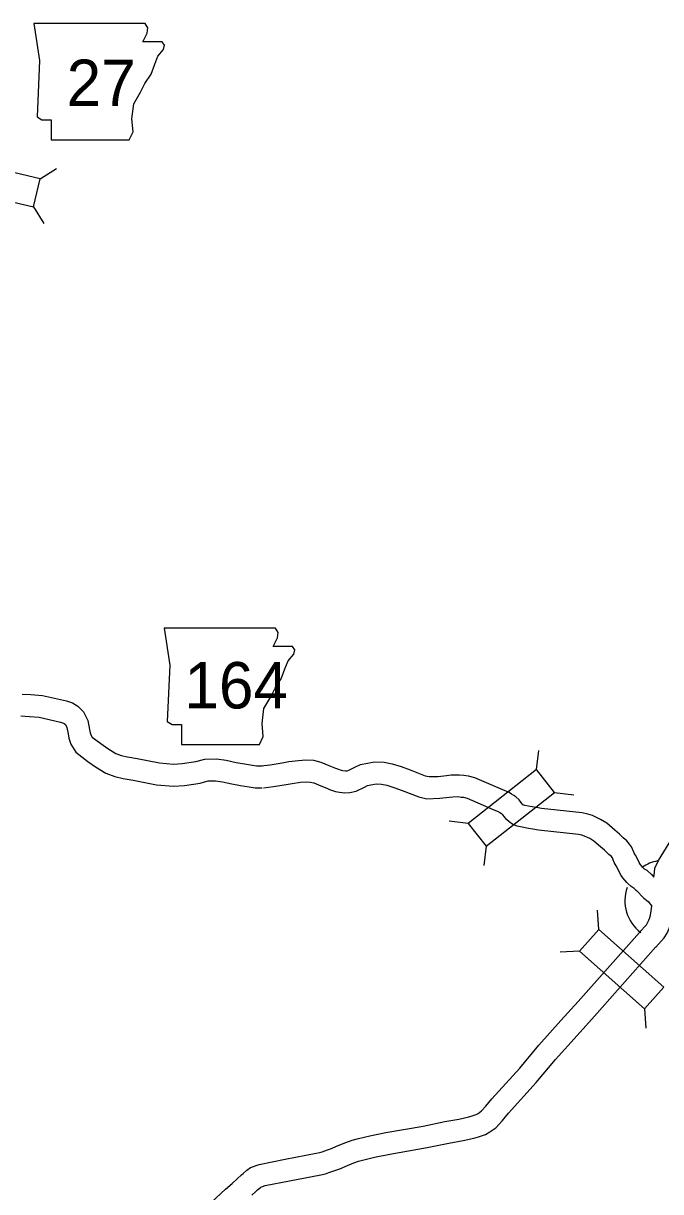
# Model space of a CAD drawing. Extents: x 1374139 to 1377472, y 1168351 to 1170484.
# Drawn here: x 1374646.9 to 1374734, y 1170176.4 to 1170336 of the extents above; entities that cross this region are included whole.
import ezdxf

# ---------------------------------------------------------------- set-up
doc = ezdxf.new("R2010")
doc.units = 0
doc.layers.add('Default', color=7, linetype='Continuous')

msp = doc.modelspace()

# ---------------------------------------------------------------- linework, layer by layer
at = {"layer": 'Default'}
for p, q in [((1374649.22, 1170314.78), (1374651.46, 1170316.17)), ((1374648.31, 1170310.92), (1374649.71, 1170308.68)), ((1374717.02, 1170234.05), (1374717.33, 1170236.67)), ((1374719.47, 1170230.94), (1374722.09, 1170230.62)), ((1374707.68, 1170226.7), (1374705.06, 1170227.01)), ((1374710.13, 1170223.59), (1374709.82, 1170220.96)), ((1374725.5, 1170212.22), (1374725.34, 1170214.86)), ((1374722.88, 1170209.26), (1374720.24, 1170209.1)), ((1374731.76, 1170201.38), (1374731.92, 1170198.74))]:
    msp.add_line(p, q, dxfattribs=at)
for points in [[(1374648.38, 1170336.01), (1374649.14, 1170330.93), (1374648.8, 1170323.23), (1374649.48, 1170322.81), (1374650.75, 1170322.81), (1374650.75, 1170320.1), (1374661.4, 1170320.1), (1374661.91, 1170321.2), (1374661.74, 1170322.98), (1374662, 1170325.01), (1374662.93, 1170326.62), (1374663.52, 1170327.8), (1374664.37, 1170329.07), (1374664.87, 1170330.42), (1374665.3, 1170331.52), (1374666.06, 1170332.45), (1374666.23, 1170333.05), (1374665.89, 1170333.47), (1374663.27, 1170333.47), (1374663.86, 1170334.65), (1374663.94, 1170335.41), (1374663.59, 1170336)], [(1374649.22, 1170314.78), (1374637.65, 1170317.48), (1374636.75, 1170313.62), (1374648.31, 1170310.92)], [(1374666.17, 1170253.39), (1374666.93, 1170248.32), (1374666.59, 1170240.62), (1374667.27, 1170240.2), (1374668.53, 1170240.2), (1374668.53, 1170237.49), (1374679.19, 1170237.49), (1374679.7, 1170238.59), (1374679.53, 1170240.37), (1374679.79, 1170242.4), (1374680.72, 1170244.01), (1374681.31, 1170245.19), (1374682.15, 1170246.46), (1374682.66, 1170247.81), (1374683.08, 1170248.91), (1374683.85, 1170249.84), (1374684.01, 1170250.43), (1374683.68, 1170250.86), (1374681.05, 1170250.86), (1374681.65, 1170252.04), (1374681.73, 1170252.8), (1374681.38, 1170253.39)], [(1374710.13, 1170223.59), (1374719.47, 1170230.94), (1374717.02, 1170234.05), (1374707.68, 1170226.7)], [(1374722.88, 1170209.26), (1374731.76, 1170201.38), (1374734.39, 1170204.34), (1374725.5, 1170212.22)]]:
    msp.add_lwpolyline(points, close=True, dxfattribs=at)
for points in [[(1374646.79, 1170244.37), (1374647.97, 1170244.32), (1374649.56, 1170244.18), (1374652.82, 1170243.44), (1374653.65, 1170243.16), (1374654.37, 1170242.74), (1374655.17, 1170241.95), (1374655.72, 1170240.77), (1374655.99, 1170239.53), (1374656.06, 1170239.1), (1374656.17, 1170238.79), (1374656.35, 1170238.5), (1374657.52, 1170237.6), (1374658.45, 1170236.95), (1374659.55, 1170236.26), (1374660.29, 1170235.99), (1374661.15, 1170235.79), (1374662.48, 1170235.59), (1374665.53, 1170234.96), (1374667.45, 1170234.8), (1374668.6, 1170234.88), (1374670.49, 1170235.16), (1374671.73, 1170235.5), (1374673.32, 1170235.52), (1374674.65, 1170235.35), (1374676, 1170235.03), (1374677.12, 1170234.84), (1374678.23, 1170234.64), (1374678.78, 1170234.57), (1374679.53, 1170234.57)], [(1374646.61, 1170241.38), (1374647.78, 1170241.33), (1374649.09, 1170241.21), (1374652.01, 1170240.55), (1374652.4, 1170240.42), (1374652.53, 1170240.34), (1374652.67, 1170240.2), (1374652.86, 1170239.81), (1374653.04, 1170238.95), (1374653.15, 1170238.34), (1374653.44, 1170237.51), (1374654.09, 1170236.45), (1374655.75, 1170235.18), (1374656.79, 1170234.45), (1374658.22, 1170233.56), (1374659.42, 1170233.11), (1374660.58, 1170232.84), (1374661.95, 1170232.63), (1374665.1, 1170231.99), (1374667.44, 1170231.79), (1374668.93, 1170231.9), (1374671.1, 1170232.22), (1374672.16, 1170232.5), (1374673.15, 1170232.52), (1374674.11, 1170232.39), (1374675.4, 1170232.09), (1374676.6, 1170231.88), (1374677.76, 1170231.68), (1374678.59, 1170231.57), (1374679.55, 1170231.57)], [(1374679.36, 1170234.56), (1374680.66, 1170234.72), (1374682.29, 1170234.98), (1374683.18, 1170235.14), (1374684.5, 1170235.31), (1374685.5, 1170235.38), (1374686.54, 1170235.35), (1374687.54, 1170235.08), (1374688.66, 1170234.63), (1374689.58, 1170234.27), (1374689.85, 1170234.14), (1374690.33, 1170233.98), (1374690.58, 1170233.93), (1374690.91, 1170233.89), (1374691.13, 1170233.9), (1374691.37, 1170233.96), (1374692.2, 1170234.37), (1374692.99, 1170234.74), (1374694.89, 1170235.11), (1374696.19, 1170235.06), (1374697.29, 1170234.86), (1374698.52, 1170234.46), (1374699.74, 1170234.01), (1374701.82, 1170233.21), (1374702.34, 1170233.09), (1374703.57, 1170233.12), (1374704.7, 1170233.25), (1374705.34, 1170233.35), (1374706.45, 1170233.36), (1374707.08, 1170233.29), (1374707.66, 1170233.22), (1374708.55, 1170232.96), (1374712.36, 1170231.32)], [(1374679.72, 1170231.58), (1374681.08, 1170231.75), (1374682.8, 1170232.02), (1374683.64, 1170232.17), (1374684.79, 1170232.32), (1374685.55, 1170232.37), (1374686.11, 1170232.36), (1374686.59, 1170232.23), (1374687.55, 1170231.84), (1374688.38, 1170231.52), (1374688.73, 1170231.35), (1374689.54, 1170231.08), (1374690.11, 1170230.96), (1374690.83, 1170230.88), (1374691.52, 1170230.92), (1374692.36, 1170231.1), (1374693.51, 1170231.67), (1374693.93, 1170231.87), (1374695.12, 1170232.1), (1374695.86, 1170232.07), (1374696.56, 1170231.94), (1374697.54, 1170231.62), (1374698.68, 1170231.21), (1374700.94, 1170230.33), (1374702.05, 1170230.08), (1374703.79, 1170230.13), (1374705.1, 1170230.28), (1374705.58, 1170230.35), (1374706.3, 1170230.36), (1374706.73, 1170230.31), (1374707.04, 1170230.27), (1374707.53, 1170230.13), (1374711.18, 1170228.57)], [(1374732.69, 1170219.73), (1374732.1, 1170220.25), (1374731.76, 1170220.45), (1374731.56, 1170220.65), (1374731.5, 1170220.71), (1374731.34, 1170220.89), (1374731.19, 1170221.07), (1374731.15, 1170221.14), (1374731.03, 1170221.36), (1374730.82, 1170221.78), (1374730.5, 1170222.37), (1374730.33, 1170222.66), (1374730.29, 1170222.79), (1374729.99, 1170223.51), (1374729.72, 1170223.87), (1374729.36, 1170224.33), (1374728.86, 1170224.72), (1374728.33, 1170225.24), (1374727.7, 1170225.78), (1374726.59, 1170226.75), (1374725.75, 1170227.23), (1374725.31, 1170227.48), (1374724.64, 1170227.78), (1374724.01, 1170227.98), (1374723.25, 1170228.17), (1374717.69, 1170228.75), (1374717.01, 1170228.87), (1374716.42, 1170228.98), (1374715.43, 1170229.15), (1374715.26, 1170229.2), (1374715.16, 1170229.24), (1374715.15, 1170229.24), (1374715, 1170229.43), (1374714.62, 1170229.91), (1374714.17, 1170230.34), (1374713.91, 1170230.52), (1374713.6, 1170230.72), (1374713.27, 1170230.91), (1374712.39, 1170231.31)], [(1374733.04, 1170219.38), (1374733.09, 1170219.67), (1374733.1, 1170220), (1374733.17, 1170220.57), (1374733.67, 1170221.64), (1374735.14, 1170224.02), (1374735.33, 1170224.39), (1374735.84, 1170224.99), (1374736.32, 1170225.29), (1374746.81, 1170231.97)], [(1374730.68, 1170217.51), (1374730.32, 1170217.82), (1374729.91, 1170218.07), (1374729.47, 1170218.5), (1374729.33, 1170218.64), (1374729.06, 1170218.93), (1374728.78, 1170219.27), (1374728.57, 1170219.6), (1374728.36, 1170219.99), (1374728.15, 1170220.41), (1374727.9, 1170220.89), (1374727.6, 1170221.38), (1374727.48, 1170221.73), (1374727.36, 1170222.02), (1374727.35, 1170222.04), (1374727.23, 1170222.19), (1374726.89, 1170222.45), (1374726.3, 1170223.03), (1374725.73, 1170223.52), (1374724.84, 1170224.29), (1374724.27, 1170224.62), (1374723.95, 1170224.8), (1374723.57, 1170224.97), (1374723.19, 1170225.09), (1374722.72, 1170225.21), (1374717.27, 1170225.78), (1374716.49, 1170225.92), (1374715.89, 1170226.02), (1374714.82, 1170226.22), (1374714.35, 1170226.33), (1374713.77, 1170226.56), (1374713.25, 1170226.9), (1374712.92, 1170227.22), (1374712.64, 1170227.59), (1374712.4, 1170227.88), (1374712.29, 1170227.99), (1374712.23, 1170228.03), (1374712.01, 1170228.17), (1374711.9, 1170228.24), (1374711.15, 1170228.58)], [(1374732.69, 1170219.73), (1374733.04, 1170219.38)], [(1374730.6, 1170217.59), (1374731.68, 1170216.49), (1374732.23, 1170216.02), (1374732.76, 1170215.38)], [(1374731.09, 1170211.83), (1374732.02, 1170212.85), (1374732.17, 1170213.1), (1374732.34, 1170213.47), (1374732.47, 1170213.85), (1374732.57, 1170214.17), (1374732.62, 1170214.45), (1374732.65, 1170214.74), (1374732.76, 1170215.38)], [(1374733.3, 1170209.8), (1374734.45, 1170211.06), (1374734.83, 1170211.7), (1374735.13, 1170212.36), (1374735.23, 1170212.63)], [(1374670.75, 1170173.22), (1374674.55, 1170176.72), (1374675.43, 1170177.5), (1374676.11, 1170178.15), (1374676.72, 1170178.68), (1374676.97, 1170178.89), (1374677.47, 1170179.33), (1374677.97, 1170179.68), (1374679.14, 1170180.12), (1374682.69, 1170180.82), (1374686.93, 1170181.64), (1374687.42, 1170181.75), (1374687.73, 1170181.85), (1374688.47, 1170182.1), (1374689.01, 1170182.31), (1374689.71, 1170182.61), (1374690.96, 1170183.12), (1374691.82, 1170183.44), (1374692.71, 1170183.67), (1374694.23, 1170184.02), (1374696.42, 1170184.48), (1374701.52, 1170185.36), (1374704.49, 1170185.99), (1374706.39, 1170186.31), (1374707.76, 1170186.63), (1374708.21, 1170186.74), (1374708.75, 1170186.93), (1374709.02, 1170187.09), (1374709.48, 1170187.42), (1374710.1, 1170188.07), (1374710.89, 1170189.06), (1374714.72, 1170193.28), (1374717.33, 1170196.42), (1374720.33, 1170199.76), (1374722.69, 1170202.36), (1374731.07, 1170211.81)], [(1374678.13, 1170175.93), (1374678.69, 1170176.41), (1374678.93, 1170176.63), (1374679.32, 1170176.96), (1374679.38, 1170177), (1374679.97, 1170177.22), (1374683.27, 1170177.88), (1374687.54, 1170178.71), (1374688.2, 1170178.85), (1374688.67, 1170179), (1374689.48, 1170179.28), (1374690.13, 1170179.53), (1374690.87, 1170179.84), (1374692.05, 1170180.33), (1374692.72, 1170180.57), (1374693.43, 1170180.76), (1374694.87, 1170181.09), (1374696.98, 1170181.53), (1374702.08, 1170182.41), (1374705.05, 1170183.04), (1374706.98, 1170183.37), (1374708.47, 1170183.71), (1374709.08, 1170183.87), (1374710.03, 1170184.2), (1374710.65, 1170184.57), (1374711.45, 1170185.13), (1374712.37, 1170186.1), (1374713.17, 1170187.11), (1374716.98, 1170191.32), (1374719.6, 1170194.46), (1374722.56, 1170197.75), (1374724.93, 1170200.36), (1374733.32, 1170209.82)]]:
    msp.add_lwpolyline(points, dxfattribs=at)
for start, end in [(101.0442, 124.2827), (161.2552, 232.647)]:
    msp.add_arc((1374734.57, 1170216.18), 5.5, start, end, dxfattribs=at)

# ---------------------------------------------------------------- texts
for s, p in [('27', (1374652.85, 1170324.72)), ('164', (1374668.93, 1170242.41))]:
    msp.add_text(s, height=6.336, dxfattribs=at).set_placement(p)

doc.saveas('drawing.dxf')
